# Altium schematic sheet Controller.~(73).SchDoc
size OrCAD B; PageSetup: Record=PageOptions¦CenterHorizontal=True¦CenterVertical=True¦PrintScale=1.06¦XCorrection=1.00¦YCorrection=1.00¦PrintKind=0¦BorderSize=5000000¦LeftOffset=0¦BottomOffset=0¦Orientation=2¦PaperLength=1000¦PaperWidth=1000¦Scale=100¦PaperSource=7¦PrintQuality=-4¦MediaType=1¦DitherType=10¦PaperKind=11x17¦PrintScaleMode=1
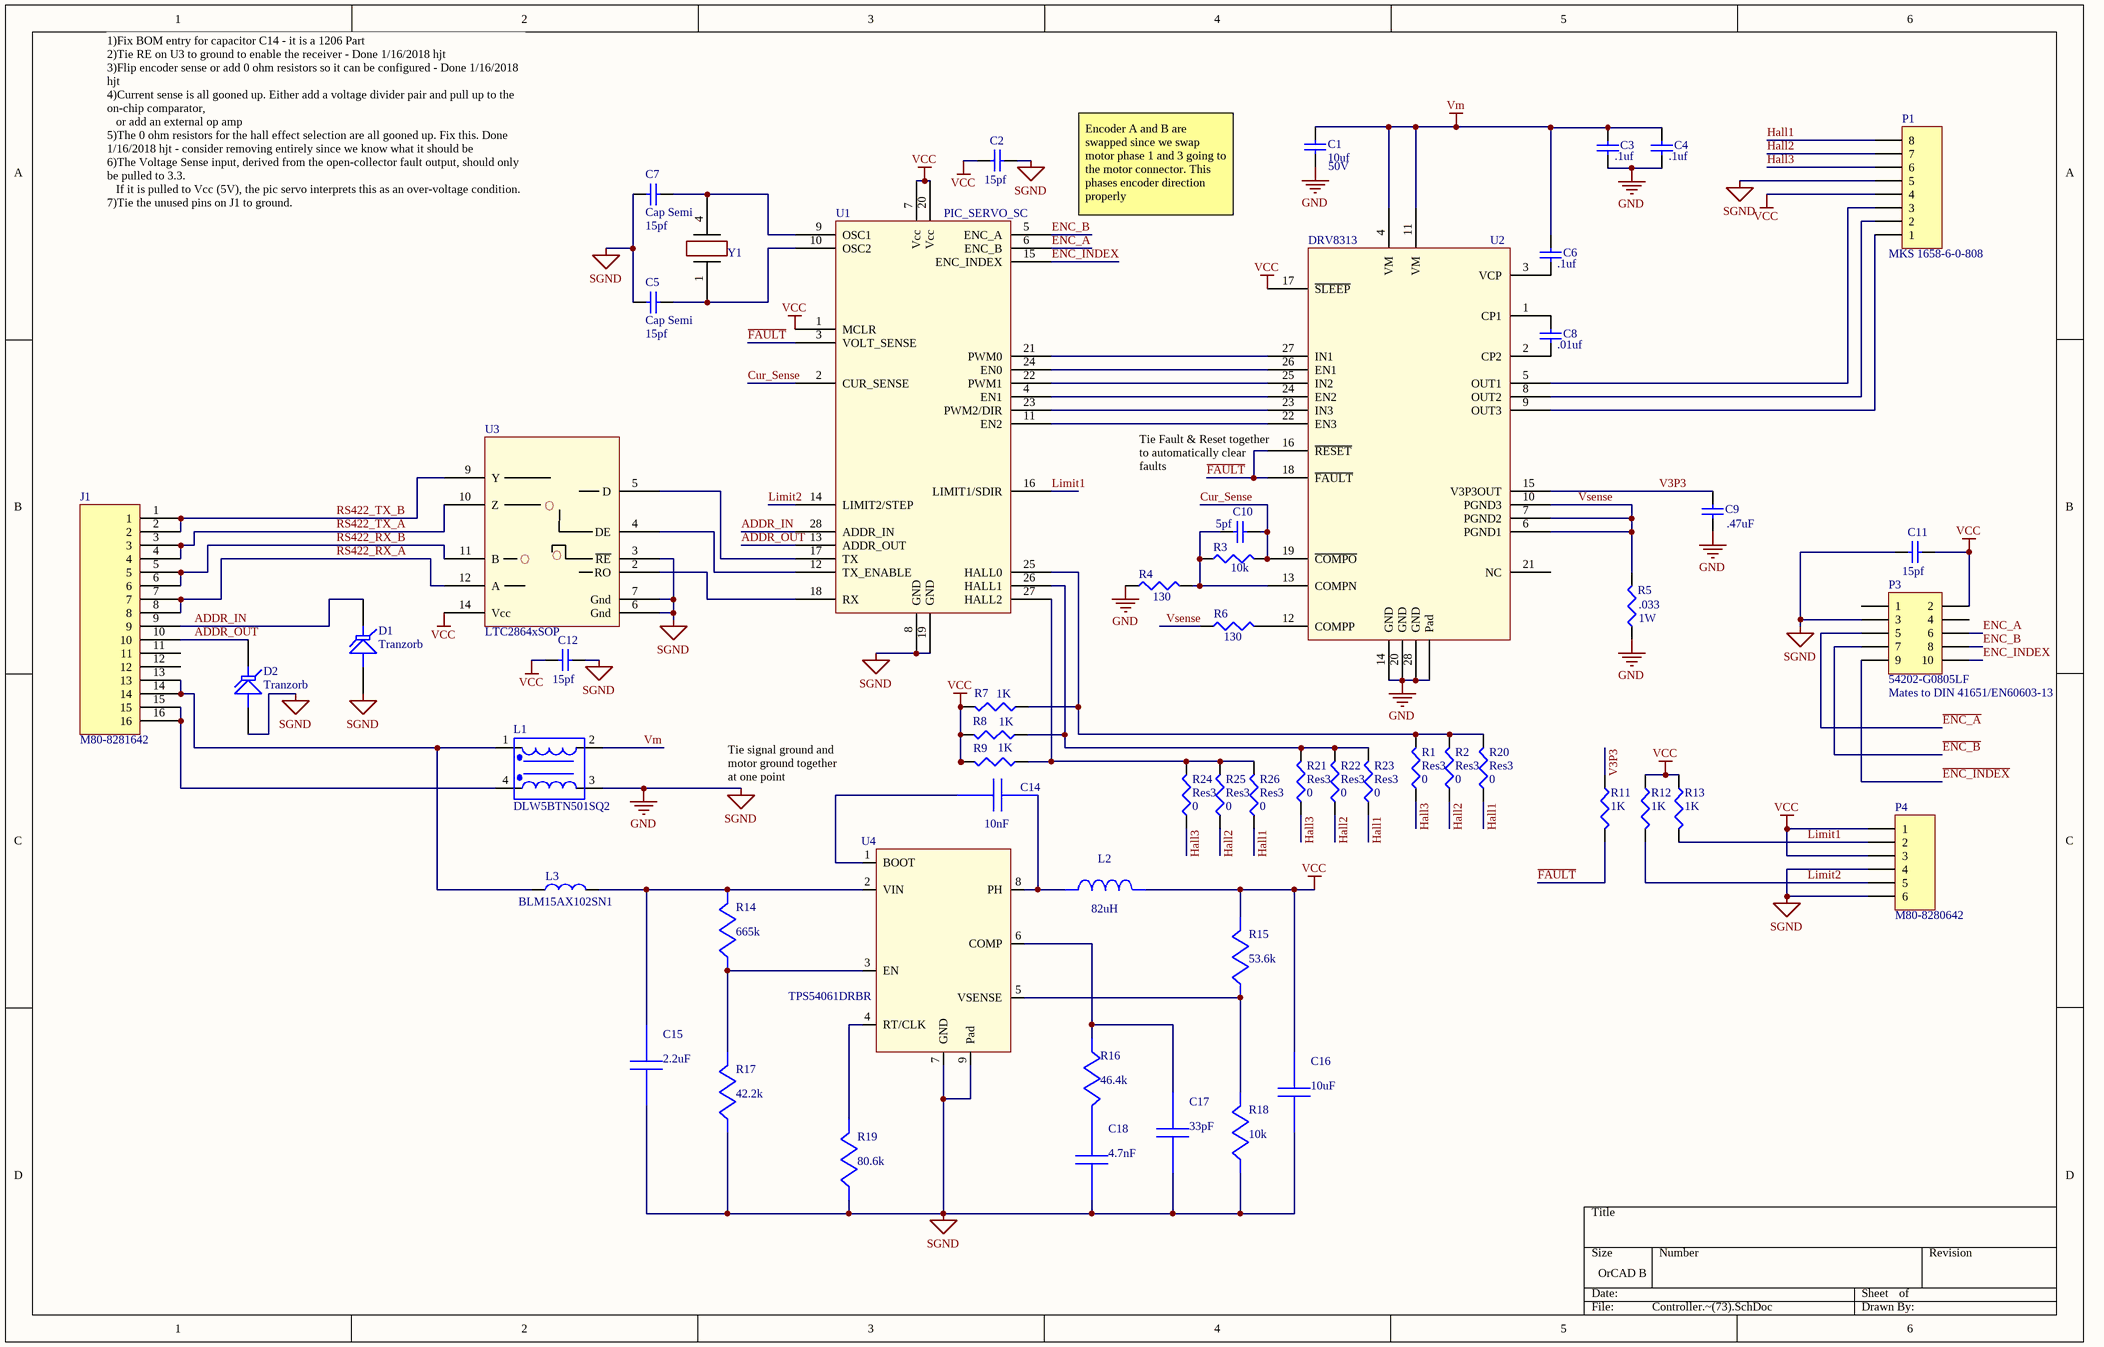
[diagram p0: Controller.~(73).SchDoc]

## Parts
C1  value 10uf  Voltage: 50V  [CAPSTICK-CS4-5-SMD]  (hidden comment: Cap)
C2  value 15pf  [1608[0603]]  (hidden comment: Cap Semi)
C3  value .1uf  [1608[0603]]  (hidden comment: Cap Semi)
C4  value .1uf  [1608[0603]]  (hidden comment: Cap Semi)
C5  Cap Semi  value 15pf  [1608[0603]]
C6  value .1uf  [1608[0603]]  (hidden comment: Cap Semi)
C7  Cap Semi  value 15pf  [1608[0603]]
C8  value .01uf  [1608[0603]]  (hidden comment: Cap Semi)
C9  value .47uF  [1608[0603]]  (hidden comment: Cap Semi)
C10  value 5pf  [1608[0603]]  (hidden comment: Cap Semi)
C11  value 15pf  [1608[0603]]  (hidden comment: Cap Semi)
C12  value 15pf  [1608[0603]]  (hidden comment: Cap Semi)
C14  value 10nF  [C1206]  (hidden comment: C1005X7R1E103K)
C15  value 2.2uF  [1210]  (hidden comment: C3225X7R2A225K230AB)
C16  value 10uF  [0603]  (hidden comment: C1608X5R0J106M)
C17  value 33pF  [0402]  (hidden comment: C0402C330J5GAC)
C18  value 4.7nF  [0201]  (hidden comment: GRM033R61A472KA01D)
D1  Tranzorb  [0402]
D2  Tranzorb  [0402]
J1  M80-8281642  [M80-828XXXXDIL]
L1  DLW5BTN501SQ2  [DLW5A_5B]
L2  value 82uH  [LPS5030]  (hidden comment: LPS5030-823MLB)
L3  PartNo: BLM15AX102SN1  [0402]  (hidden comment: INDUCTOR)
P1  MKS 1658-6-0-808  [MKS_1658_A_KF]
P3  54202-G0805LF  [N2510_SMD]
P4  M80-8280642  [M8082806DIL]
R1  Res3  value 0  [J1-0603]
R2  Res3  value 0  [J1-0603]
R3  value 10k  [J1-0603]  (hidden comment: Res3)
R4  value 130  [J1-0603]  (hidden comment: Res3)
R5  value .033  Pwr: 1W  [1206]  (hidden comment: Res3)
R6  value 130  [J1-0603]  (hidden comment: Res3)
R7  value 1K  [J1-0603]  (hidden comment: Res3)
R8  value 1K  [J1-0603]  (hidden comment: Res3)
R9  value 1K  [J1-0603]  (hidden comment: Res3)
R11  value 1K  [J1-0603]  (hidden comment: Res3)
R12  value 1K  [J1-0603]  (hidden comment: Res3)
R13  value 1K  [J1-0603]  (hidden comment: Res3)
R14  value 665k  [0402]  (hidden comment: CRCW0402665KFKED)
R15  value 53.6k  [0402]  (hidden comment: CRCW040253K6FKED)
R16  value 46.4k  [0402]  (hidden comment: CRCW040246K4FKED)
R17  value 42.2k  [0402]  (hidden comment: CRCW040242K2FKED)
R18  value 10k  [0402]  (hidden comment: CRCW040210K0FKED)
R19  value 80.6k  [0402]  (hidden comment: CRCW040280K6FKED)
R20  Res3  value 0  [J1-0603]
R21  Res3  value 0  [J1-0603]
R22  Res3  value 0  [J1-0603]
R23  Res3  value 0  [J1-0603]
R24  Res3  value 0  [J1-0603]
R25  Res3  value 0  [J1-0603]
R26  Res3  value 0  [J1-0603]
U1  PIC_SERVO_SC  [SOP28]
U2  DRV8313  [HTSSOP28]
U3  LTC2864xSOP  [SOP14]
U4  TPS54061DRBR  [S-PVSON-N8]
Y1  MA-506 10.0000M-C0  [MA506]  (value not drawn)

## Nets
GND: C1.2 C2.2 C3.1 C4.1 C5.1 C7.1 C9.1 C11.1 C12.2 C15.2 C16.2 C17.2 C18.2 D1.1(A) D2.1(A) L1.3 P1.5 P3.3 P4.4 P4.6 R4.1 R5.1 R17.2 R18.2 R19.2 U1.8(GND) U1.19(GND) U2.14(GND) U2.20(GND) U2.28(GND) U2.Pad U3.3(~{RE}) U3.6(Gnd) U3.7(Gnd) U4.7(GND) U4.9(Pad)  [also labelled SGND]
VCC: C2.1 C11.2 C12.1 C16.1 L2.1 P1.4 P3.2 P4.1 P4.3 R7.2 R8.2 R9.2 R12.1 R13.1 R15.1 U1.1(MCLR) U1.7(Vcc) U1.20(Vcc) U2.17(~{SLEEP}) U3.14(Vcc)
Vm: C1.1 C3.2 C4.2 C6.2 L1.2 U2.4(VM) U2.11(VM)
~{ENC_A}: P3.5
~{ENC_B}: P3.7
~{ENC_INDEX}: P3.9
~{FAULT}: R11.2 U1.3(VOLT_SENSE) U2.16(~{RESET}) U2.18(~{FAULT})
ADDR_IN: D1.2(K) J1.9 U1.28(ADDR_IN)
ADDR_OUT: D2.2(K) J1.10 U1.13(ADDR_OUT)
Cur_Sense: C10.1 R3.2 U1.2(CUR_SENSE) U2.19(~{COMPO})
ENC_A: P3.6 U1.6(ENC_B)
ENC_B: P3.8 U1.5(ENC_A)
ENC_INDEX: P3.10 U1.15(ENC_INDEX)
Hall1: P1.8 R20.1 R23.1 R26.1
Hall2: P1.7 R2.1 R22.1 R25.1
Hall3: P1.6 R1.1 R21.1 R24.1
Limit1: P4.2 R13.2 U1.16(LIMIT1/SDIR)
Limit2: P4.5 R12.2 U1.14(LIMIT2/STEP)
RS422_RX_A: J1.7 J1.8 U3.12(A)
RS422_RX_B: J1.5 J1.6 U3.11(B)
RS422_TX_A: J1.3 J1.4 U3.10(Z)
RS422_TX_B: J1.1 J1.2 U3.9(Y)
V3P3: C9.2 R11.1 U2.15(V3P3OUT)
Vsense: R5.2 R6.1 U2.6(PGND1) U2.7(PGND2) U2.10(PGND3)
NetC5_2: C5.2 U1.10(OSC2) Y1.1
NetC6_1: C6.1 U2.3(VCP)
NetC7_2: C7.2 U1.9(OSC1) Y1.4
NetC8_1: C8.1 U2.2(CP2)
NetC8_2: C8.2 U2.1(CP1)
NetC10_2: C10.2 R3.1 R4.2 U2.13(COMPN)
NetC14_1: C14.1 L2.2 U4.8(PH)
NetC14_2: C14.2 U4.1(BOOT)
NetC15_1: C15.1 L3.2 R14.1 U4.2(VIN)
NetC17_1: C17.1 R16.2 U4.6(COMP)
NetC18_1: C18.1 R16.1
NetJ1_13: J1.13 J1.14 L1.1 L3.1
NetJ1_15: J1.15 J1.16 L1.4
NetP1_1: P1.1 U2.9(OUT3)
NetP1_2: P1.2 U2.8(OUT2)
NetP1_3: P1.3 U2.5(OUT1)
NetR1_2: R1.2 R2.2 R7.1 R20.2 U1.25(HALL0)
NetR6_2: R6.2 U2.12(COMPP)
NetR8_1: R8.1 R21.2 R22.2 R23.2 U1.26(HALL1)
NetR9_1: R9.1 R24.2 R25.2 R26.2 U1.27(HALL2)
NetR14_2: R14.2 R17.1 U4.3(EN)
NetR15_2: R15.2 R18.1 U4.5(VSENSE)
NetR19_1: R19.1 U4.4(RT/CLK)
NetU1_4: U1.4(EN1) U2.24(EN2)
NetU1_11: U1.11(EN2) U2.22(EN3)
NetU1_12: U1.12(TX_ENABLE) U3.4(DE)
NetU1_17: U1.17(TX) U3.5(D)
NetU1_18: U1.18(RX) U3.2(RO)
NetU1_21: U1.21(PWM0) U2.27(IN1)
NetU1_22: U1.22(PWM1) U2.25(IN2)
NetU1_23: U1.23(PWM2/DIR) U2.23(IN3)
NetU1_24: U1.24(EN0) U2.26(EN1)

Not connected (* = marked no-connect by the designer): J1 11 12; P3 1 4; U2 21(NC); U3 1(NC) 8(NC) 13(NC)

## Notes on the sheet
- Encoder A and B are swapped since we swap motor phase 1 and 3 going to the motor connector. This phases encoder direction properly
- 1)Fix BOM entry for capacitor C14 - it is a 1206 Part
  2)Tie RE on U3 to ground to enable the receiver - Done 1/16/2018 hjt
  3)Flip encoder sense or add 0 ohm resistors so it can be configured - Done 1/16/2018 hjt
  4)Current sense is all gooned up. Either add a voltage divider pair and pull up to the on-chip comparator,
  or add an external op amp
  5)The 0 ohm resistors for the hall effect selection are all gooned up. Fix this. Done 1/16/2018 hjt - consider removing entirely since we know what it should be
  6)The Voltage Sense input, derived from the open-collector fault output, should only be pulled to 3.3.
  If it is pulled to Vcc (5V), the pic servo interprets this as an over-voltage condition.
  7)Tie the unused pins on J1 to ground.
- (near U2) Tie Fault & Reset together
  to automatically clear faults
- (near P3) Mates to DIN 41651/EN60603-13
- Tie signal ground and
  motor ground together
  at one point

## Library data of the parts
C1 = Cap: Capacitor; Manufacturer: ITW Paktron; PartNo: 106K050CS4G
C2 = Cap Semi: Capacitor; PartNo: C0603C150M8GACTU; Manufacturer: Kemet
C3 C4 = Cap Semi: Capacitor; Manufacturer: Yageo; PartNo: CC0603KRX7R9BB104
C5 C7 = Cap Semi: Capacitor (Semiconductor SIM Model); Manufacturer: Kemet; PartNo: C0603C150M8GACTU
C6 = Cap Semi: Capacitor (Semiconductor SIM Model); Manufacturer: Yageo; PartNo: CC0603KRX7R9BB104
C8 = Cap Semi: Capacitor (Semiconductor SIM Model); Manufacturer: Kemet; PartNo: C0603C103K5RACTU
C9 = Cap Semi: Capacitor (Semiconductor SIM Model); Manufacturer: TDK Corporation; PartNo: C1608X7R1H474K080AC
C10 = Cap Semi: Capacitor (Semiconductor SIM Model); Manufacturer: TDK Corporation; PartNo: C1608C0G1H050C080AA
C11 C12 = Cap Semi: Capacitor (Semiconductor SIM Model); PartNo: C0603C150M8GACTU; Manufacturer: Kemet
C14 = C1005X7R1E103K: Manufacturer: TDK Corporation
C15 = C3225X7R2A225K230AB: C3225X7R2A225K23; Manufacturer: TDK Corporation
C16 = C1608X5R0J106M: Manufacturer: TDK Corporation
C17 = C0402C330J5GAC: Manufacturer: Kemet
C18 = GRM033R61A472KA01D: GRM033R61A472KA0; Manufacturer: MuRata
D1 D2 = Tranzorb: Transient Voltage Suppression (TVS) Diode; Manufacturer: Comchip; PartNo: CPDQR5V0
J1 = M80-8281642: Manufacturer: Harwin
L1 = COMMON MODE CHOKE: Manufacturer: Murata
L2 = LPS5030-823MLB: Manufacturer: Coilcraft
L3 = INDUCTOR: Manufacturer: Murata
P1 = Header 8: Manufacturer: Stocko
P3 = Header 5X2: Header, 10-Pin, Dual row; Manufacturer: FCI
P4 = Header 6: Header, 6-Pin; Manufacturer: Harwin
R1 R2 R20-R26 = Res3: Resistor; Manufacturer: Vishay Dale; PartNo: CRCW06030000Z0EA
R3 = Res3: Resistor; Manufacturer: Vishay Dale; PartNo: CRCW060310K0DHEAP
R4 R6 = Res3: Resistor; Manufacturer: Vishay Dale; PartNo: CRCW0603130RFKEA
R5 = Res3: Resistor; PartNo: ERJ-8BWFR033V; Manufacturer: Panasonic
R7-R9 R11-R13 = Res3: Resistor; Manufacturer: Vishay Dale; PartNo: CRCW06031K00FKEA
R14 = CRCW0402665KFKED: Manufacturer: Vishay-Dale
R15 = CRCW040253K6FKED: Manufacturer: Vishay-Dale
R16 = CRCW040246K4FKED: Manufacturer: Vishay-Dale
R17 = CRCW040242K2FKED: Manufacturer: Vishay-Dale
R18 = CRCW040210K0FKED: Manufacturer: Vishay-Dale
R19 = CRCW040280K6FKED: Manufacturer: Vishay-Dale
U1 = PIC_SERVO_SC: PartNo: KAE-T0V10-SO; Manufacturer: jrkerr
U2 = DRV8313: PartNo: DRV8313PWPR; Manufacturer: Texas Instruments
U3 = LTC2864xSOP: PartNo: LTC2864IS-1#PBF; Manufacturer: Linear Tech
U4 = TPS54061DRBR: Imported; Frequency: 1100000.0; Imax: 0.2; Vendor: Texas Instruments
Y1 = MA-406/MA-505/MA-506: Manufacturer: Epson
